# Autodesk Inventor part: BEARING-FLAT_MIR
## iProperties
Created: 2007-08
Part Number: BEARING-FLAT_MIR
Material: Delrin, Black
Document SubType Name: Modeling
Density: 1.425 g/cm^3
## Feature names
1. Derived Body1 [Tagging]
